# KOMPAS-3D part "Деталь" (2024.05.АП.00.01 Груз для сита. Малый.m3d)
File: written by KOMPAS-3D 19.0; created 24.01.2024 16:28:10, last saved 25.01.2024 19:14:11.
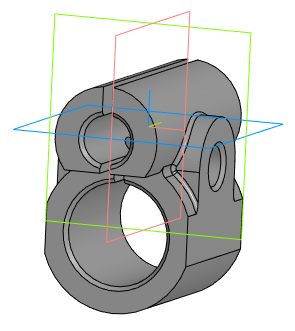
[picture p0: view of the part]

Document properties: Автор: mail.maksim@mail.ru; Полное имя файла: O:\Самозанятый. Полынский М.И\Агропак\2024.05.АП.00.00 Грузы для сита. Хартманн 1 и 2\2024.05.АП.00.00 Чертежи\2024.05.АП 3D модели\2024.05.АП.00.01 Груз для сита. Малый.m3d

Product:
- Part/product: Деталь
    Масса: 0.322187
  - Body: Тело 1
      Масса: 0.334992

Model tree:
1. Эскиз:1
2. Элемент выдавливания:1
     Расстояние 1 = 37
3. Эскиз:2  (with: Элемент выдавливания:1)
4. Элемент выдавливания:2
     Расстояние 1 = 10
5. Эскиз:3  (with: Элемент выдавливания:1)
6. Элемент выдавливания:3
     Расстояние 1 = 10
7. Эскиз:4  (with: Элемент выдавливания:3, Элемент выдавливания:1)
8. Эскиз:6  (with: Элемент выдавливания:1)
9. Элемент выдавливания:6
     Расстояние 2 = 37
10. Эскиз:7  (with: Элемент выдавливания:6)
11. Элемент выдавливания:7
     Расстояние 2 = 36
12. Эскиз:8  (with: Элемент выдавливания:6, Элемент выдавливания:7)
13. Элемент выдавливания:8
     Расстояние 2 = 36
14. Элемент выдавливания:9
     Расстояние 2 = 63
15. Скругление:1  (with: Элемент выдавливания:1)
     Радиус = 2
16. Скругление:2  (with: Элемент выдавливания:1)
     Радиус = 2
17. Скругление:3  (with: Элемент выдавливания:7)
     Радиус = 1
18. Скругление:4  (with: Элемент выдавливания:7)
     Радиус = 1
19. Фаска:1  (with: Элемент выдавливания:7, Элемент выдавливания:9)
     Угол = 45; Длина 1 = 1; Длина 2 = 1
20. Эскиз:9  (with: Элемент выдавливания:3)
21. Элемент выдавливания:10
     Расстояние 2 = 57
